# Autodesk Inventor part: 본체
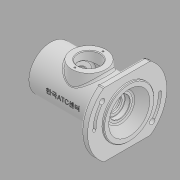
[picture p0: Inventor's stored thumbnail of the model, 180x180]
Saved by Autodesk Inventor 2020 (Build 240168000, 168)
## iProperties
Created: 2022-05
Part Number: 본체
Material: 일반
Document SubType Name: Modeling
Designer: User
Density: 1 g/cm^3
Appearance: 기본값
Author: User
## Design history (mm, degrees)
sketch "스케치1"
  geometry: L1 (0, 0)-(-102, 0); L2 (-102, 0)-(-102, 32); L3 (-102, 32)-(0, 32); L4 (0, 32)-(0, 0); L5 (0, 32)-(0, 37); L6 (0, 37)-(13, 37); L7 (13, 37)-(13, 0); L8 (13, 0)-(0, 0)
  constraints: 16 end point, 3 perpendicular, 2 parallel, 1 collinear, 1 horizontal, 1 vertical
  dimensions: "d1" = 64 diameter of L3 L1; "d4" = 102 distance of L2.end L3.end; "d5" = 74 diameter of L6 L8; "d6" = 13 distance of L5.end L6.end
revolve "회전1" sketch "스케치1" stored, may be unused: angle "d7" = 90 deg
node "작업 평면1"
sketch "스케치2" dims "d11" = 96
  geometry: L1 (-33.985, 47)-(-33.985, -47); L2 (33.985, 47)-(33.985, -47); L3 (33.985, 47)-(-33.985, 47); L4 (-33.985, -47)-(33.985, -47); L5 (0, 0)-(36.77, 30.854); A1 r 58 centre (0, 0) between (-33.985, 47) and (-33.985, -47); A2 r 58 centre (0, 0) between (-33.985, 47) and (-33.985, -47); A3 r 58 centre (0, 0) between (33.985, -47) and (33.985, 47); 2 further points
  constraints: 10 end point, 8 point on circle, 3 centre point, 2 coincident, 2 concentric, 2 horizontal, 2 vertical, 1 horizontal alignment, 1 midpoint, 1 parallel, 3 other
  dimensions: "d9" = 116 diameter of A1; "d10" = 94 distance of L1.start L1.end; "d12" = 40 deg angle of L4 L5
extrude "돌출1" join sketch "스케치2" distance "d14" = 10; taper "d15" = 0 deg
node "작업 평면2"
sketch "스케치4"
  geometry: L1 (102, 32)-(102, -32) reference; C1 r 25 at (46, 0); 2 further points
  constraints: 1 centre point, 1 horizontal alignment, 1 midpoint
  dimensions: "d27" = 50 diameter of C1; "d28" = 56 distance of C1.centre point (102, 0)
extrude "돌출2" join sketch "스케치4" stored distance "d29" = 10; taper "d30" = 5 deg
sketch "스케치5"
  geometry: L1 (-102, -32)-(-102, 32) reference; L2 (13, -37)-(13, 37) reference; L3 (-102, 0)-(13, 0); L4 (-102, 0)-(-102, 22.5); L5 (-102, 22.5)-(-94, 22.5); L6 (-94, 22.5)-(-94, 24); L7 (-94, 24)-(-91, 24); L8 (-91, 24)-(-91, 22.5); L9 (-91, 22.5)-(-80, 22.5); L10 (-80, 22.5)-(-80, 17.5); L11 (-80, 17.5)-(-77.75, 17.5); L12 (-77.75, 17.5)-(-77.75, 18.5); L13 (-77.75, 18.5)-(-76, 18.5); L14 (-76, 18.5)-(-76, 17.5); L15 (-76, 17.5)-(-65, 17.5); L16 (-65, 17.5)-(-65, 27); L17 (-65, 27)-(-27, 27); L18 (-27, 27)-(-27, 17.5); L19 (-27, 17.5)-(-16, 17.5); L20 (-16, 17.5)-(-16, 15); L21 (-16, 15)-(-11, 15); L22 (-11, 15)-(-11, 11); L23 (-11, 11)-(-8.4, 11); L24 (-8.4, 11)-(-8.4, 15); L25 (-8.4, 15)-(-1, 15); L26 (-1, 15)-(-1, 20); L27 (-1, 20)-(13, 30); L28 (13, 0)-(13, 30); 1 further point
  constraints: 52 end point, 19 perpendicular, 6 point on line, 2 midpoint, 1 collinear, 1 horizontal
  dimensions: "d31" = 45 diameter of L5 L3; "d32" = 48 diameter of L7 L3; "d33" = 8 distance of L4.end L5.end; "d34" = 22 distance between parallel lines of L10 L1; "d35" = 3 distance of L6.end L7.end; "d36" = 45 diameter of L9 L3; "d37" = 4 distance between parallel lines of L14 L10; "d39" = 37 diameter of L13 L3; "d40" = 11 distance between parallel lines of L16 L14; "d41" = 35 diameter of L11 L3; "d42" = 54 diameter of L17 L3; "d43" = 38 distance between parallel lines of L18 L16; "d44" = 11 distance of L18.end L19.end; "d45" = 5 distance of L20.end L21.end; "d46" = 30 diameter of L21 L3; "d47" = 22 diameter of L23 L3; "d48" = 30 diameter of L25 L3; "d49" = 40 diameter of L26.end L3; "d50" = 60 diameter of L27.end L3; "d51" = 14 distance from line of L2 L26.end; "d52" = 7.4 distance of L24.end L25.end; "d102" = 1.75 distance of L12.end L13.end
revolve "회전2" sketch "스케치5" stored, may be unused: angle "d53" = 90 deg
sketch "스케치6"
  geometry: C1 r 25 at (0, 0) reference; 2 further points
  constraints: 1 coincident
hole "구멍2" sketch "스케치6" at (0, 0) diameter "d54" = 32; stored, may be unused: countersink angle "d58" = 90 deg, drill point angle "d60" = 118 deg; dims "d55" = 6, "d56" = 8, "d57" = 4.4, "d59" = 8
feature "스레드1" dims "d61" = 8, "d62" = 0
node "작업 평면3"
sketch "스케치8"
  geometry: L1 (0, 0)-(-48, 0); L2 (0, 0)-(-36.77, -30.854); L3 (0, 0)-(36.77, 30.854); A1 r 48 centre (0, 0) between (-48, 0) and (-36.77, -30.854); A2 r 48 centre (0, 0) between (-48, 0) and (-36.77, -30.854); A3 r 52 centre (0, 0) between (-52, 0) and (-39.834, -33.425); A4 r 44 centre (0, 0) between (-44, 0) and (-33.706, -28.283); A5 r 4 centre (-48, 0) between (-44, 0) and (-52, 0); A6 r 4 centre (-36.77, -30.854) between (-39.834, -33.425) and (-33.706, -28.283); A7 r 45.75 centre (0, 0) between (-45.75, 0) and (-35.047, -29.408); A8 r 2.25 centre (-48, 0) between (-45.75, 0) and (-50.25, 0); A9 r 50.25 centre (0, 0) between (-50.25, 0) and (-38.494, -32.3); A10 r 2.25 centre (-36.77, -30.854) between (-38.494, -32.3) and (-35.047, -29.408); 3 further points
  constraints: 21 point on circle, 10 centre point, 6 end point, 4 tangent, 3 coincident, 1 horizontal, 1 point on line, 6 other
  dimensions: "d74" = 96 diameter of A1; "d76" = 40 deg angle of L3 L1; "d77" = 40 deg angle of L1 L2; "d80" = 4 radius of A5; "d81" = 4.5 radial gap between concentric circles of A9 A7
extrude "돌출3" cut sketch "스케치8" extent not by distance; stored distance "d82" = 4.4; taper "d83" = 0 deg
extrude "돌출4" cut sketch "스케치8" extent not by distance; stored distance "d84" = 4.4; taper "d85" = 0 deg
extrude "돌출5" cut sketch "스케치8" extent not by distance; stored distance "d86" = 4.4; taper "d87" = 0 deg
sketch "스케치9"
  geometry: L1 (0, 20.5)-(0, -20.5); C1 r 25 at (0, 0) reference; A1 r 20.5 centre (0, 0) between (0, 20.5) and (0, -20.5); 3 further points
  constraints: 3 coincident, 2 end point, 2 point on circle, 1 centre point, 1 midpoint, 1 vertical
  dimensions: "d91" = 41 diameter of A1
hole "구멍4" sketch "스케치9" at (0, 20.5), (0, -20.5) diameter "d92" = 2.459; stored, may be unused: countersink angle "d96" = 90 deg, drill point angle "d98" = 118 deg; dims "d93" = 6, "d94" = 8, "d95" = 4.4, "d97" = 8
chamfer "모따기1" distance "d99" = 0.7; stored, may be unused: second distance "d100" = 2, angle "d101" = 30 deg
fillet "모깎기1" dims "d103" = 3
fillet "모깎기2" dims "d104" = 0.6, "d105" = 0.5
chamfer "모따기2" distance "d106" = 1; stored, may be unused: second distance "d107" = 2, angle "d108" = 30 deg
fillet "모깎기3" dims "d109" = 3
fillet "모깎기4" dims "d110" = 3
node "작업 평면4"
sketch "스케치10"
  geometry: L1 (-28.15, 14.158)-(26.15, 14.158); L2 (26.15, 14.158)-(26.15, -14.158); L3 (26.15, -14.158)-(-28.15, -14.158); L4 (-28.15, -14.158)-(-28.15, 14.158); L5 (-28.15, 14.158)-(26.15, -14.158); L6 (61, -46.4)-(61, 46.4) reference; 3 further points
  constraints: 2 end point, 2 midpoint, 1 horizontal alignment, 2 other
  dimensions: "d111" = 62 distance from line of L6 point (-1, 0)
feature "엠보싱1" sketch "스케치10" dims "d1" = 64, "d4" = 102, "d5" = 74, "d6" = 13, "d9" = 116, "d10" = 94, "d11" = 96, "d12" = 40 deg, "d112" = 0.5, "d113" = 0
chamfer "모따기3" distance "d114" = 1; stored, may be unused: second distance "d115" = 2, angle "d116" = 30 deg
node "솔리드1"
pattern_circular "원형 패턴1" dims angle "d89" = 360 deg
feature "A9D066F2-1C7D-4E18-AEED-F7BC21143FA4" dims "d61" = 8, "d62" = 0
other parameters: "d8" = -3, "d26" = 38, "d73" = -4.4
